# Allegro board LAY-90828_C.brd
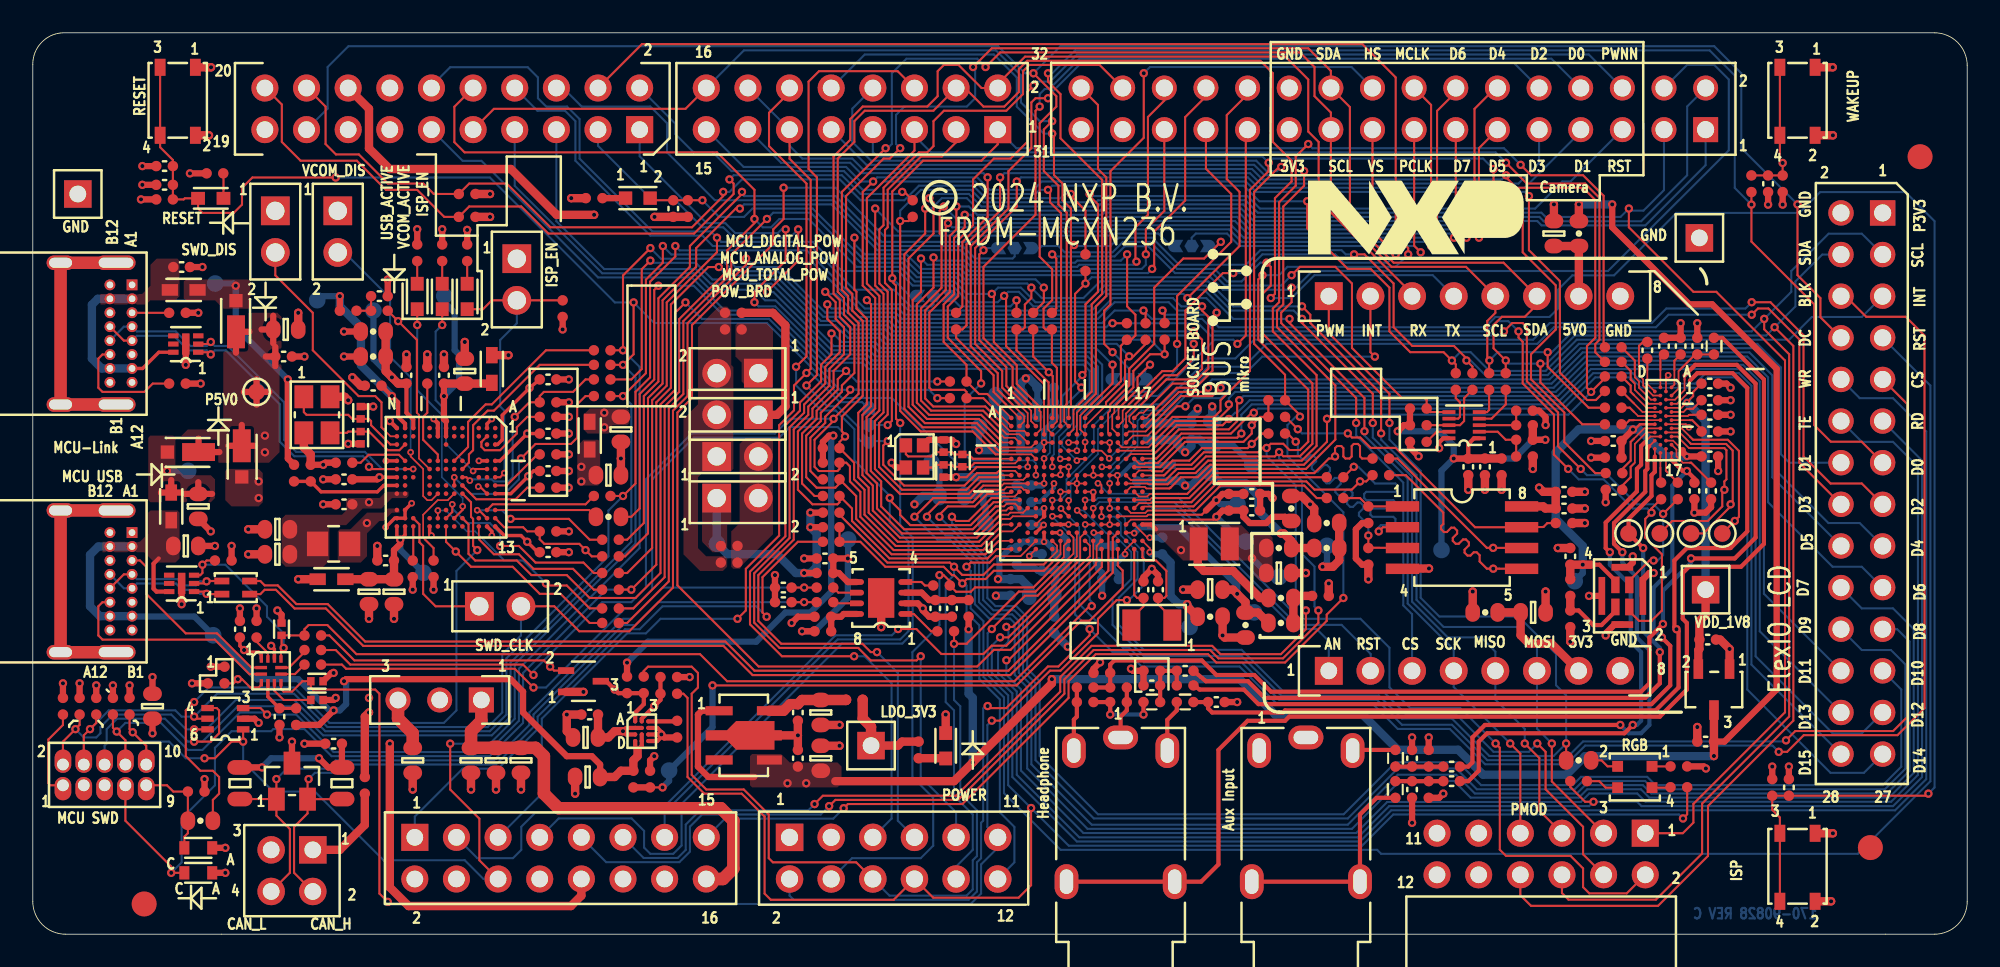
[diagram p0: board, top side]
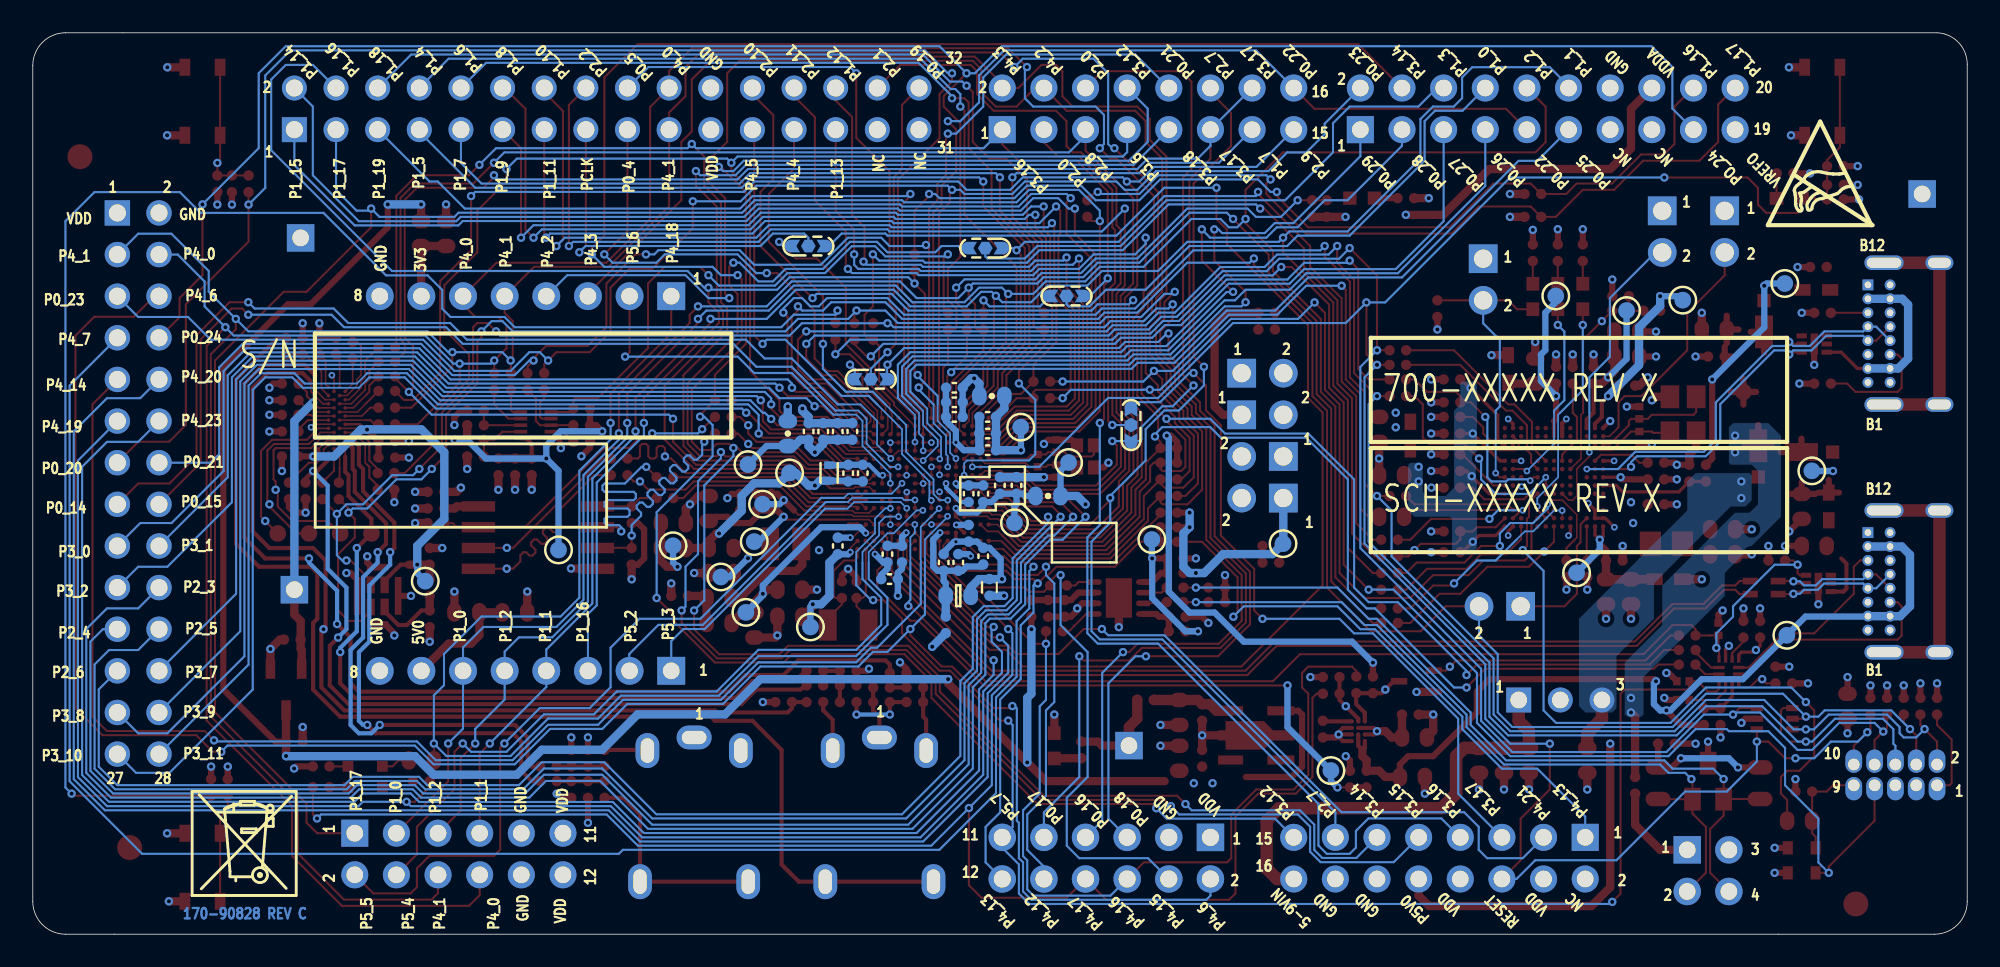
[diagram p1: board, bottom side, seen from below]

Outline 118 x 55 mm; copper layers: TOP, GND, POWER, BOTTOM. Coordinates in mm from the lower left corner of the outline.
Outline path: 0,53.08 0,2 arc(0.59,0.59) 2,0 116,0 arc(117.41,0.59) 118,2 118,53 arc(117.41,54.41) 116,55 1.84,55 arc(0.53,54.41) 0,53.08

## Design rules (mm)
constraint set DEFAULT: min track width 0.127
net group DIFFPAIR6: nets MCU_HS_USB1_DM MCU_HS_USB1_DP
net group DIFFPAIR7: nets MCU_USB1_DM MCU_USB1_DP
net group DIFFPAIR8: nets HS_USB1_DM HS_USB1_DP

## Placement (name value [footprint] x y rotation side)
BH1  125  [MH125-160]  3 3 0 top
BH2  125  [MH125-160]  115 52 0 top
BH3  125  [MH125-160]  115 3 0 top
BH4  125  [MH125-160]  3 52 0 top
C1  4.7uF  [CC0603_OV]  48.07 10.74 90 top
C2  0.1UF  [CC0402_25]  46.67 10.74 90 top
C3  0.1UF  [CC0402_25]  46.67 13.53 270 top
C4  10uF  [CC0603_OV]  48.07 13.53 270 top
C5  4.7uF  [CC0603_OV]  15.43 36.9 0 top
C6  0.1UF  [CC0402_25]  15.3 35.25 0 top
C7  1uF  [CC0402_25]  102.04 11.75 180 top
C8  1uF  [CC0402_25]  102.17 17.97 0 top
C9  0.1UF  [CC0402_25]  60.02 23.07 270 bottom
C10  1uF  [CC0402_25]  59.01 27.38 90 bottom
C11  0.1UF  [CC0402_25]  60.02 26.88 90 bottom
C12  0.1UF  [CC0402_25]  57.99 27.38 90 bottom
C13  1uF  [CC0402_25]  70.67 30.67 90 bottom
C14  0.1UF  [CC0402_25]  68.9 30.67 90 bottom
C15  0.1UF  [CC0402_25]  68.26 28.13 90 bottom
C16  0.1UF  [CC0402_25]  68.01 30.67 90 bottom
C17  0.1UF  [CC0402_25]  69.79 30.67 90 bottom
C18  4.7 uF  [CC0402_TOL0P15]  69.42 28.15 90 bottom
C19  0.1UF  [CC0402_25]  67.37 28.13 90 bottom
C20  0.1UF  [CC0402_25]  68.9 23.69 90 bottom
C21  1uF  [CC0402_25]  59.75 29.53 0 bottom
C22  0.1UF  [CC0402_25]  59.75 31.56 0 bottom
C23  0.1UF  [CC0402_25]  59.75 30.55 0 bottom
C24  1uF  [CC0402_25]  65.74 21.67 0 bottom
C25  0.1UF  [CC0402_25]  61.78 32.45 0 bottom
C26  0.1UF  [CC0402_25]  61.78 33.34 0 bottom
C27  0.1UF  [CC0402_25]  61.78 31.56 0 bottom
C28  2.2UF  [CC0402_25]  74.36 26.86 0 top
C29  0.22uF  [CC0402_25]  61.55 22.68 270 bottom
C30  1uF  [CC0402_25]  74.36 25.85 0 top
C31  1uF  [CC0402_25]  62.44 22.68 270 bottom
C32  4.7uF  [CC0603_OV]  71.82 21.02 180 top
C33  0.1UF  [CC0402_25]  65.86 23.19 270 bottom
C34  6.8uF  [CC0603_OV]  76.01 22.04 0 top
C35  0.1UF  [CC0402_25]  60.91 26.88 90 bottom
C36  4.7uF  [CC0603_OV]  9.33 23.69 0 top
C38  10uF  [CC0603_OV]  33.72 12.01 180 top
C39  0.1UF  [CC0402_25]  33.97 13.4 180 top
C40  4.7uF  [CC0603_OV]  10.1 26.1 270 top
C41  4.7uF  [CC0603_OV]  33.84 9.59 180 top
C42  1uF  [CC0402_25]  102.3 33.6 0 top
C43  1uF  [CC0402_25]  102.3 30.67 0 top
C44  1uF  [CC0402_25]  102.3 29.15 0 top
C45  1uF  [CC0402_25]  96.41 30.09 180 top
C46  100PF  [CC0402_25]  72.2 14.16 0 top
C47  0.1UF  [CC0402_25]  96.46 27.12 180 top
C48  1uF  [CC0402_25]  102.3 31.69 0 top
C49  100PF  [CC0402_25]  101.54 35.88 90 top
C50  1uF  [CC0402_25]  102.37 27.05 270 top
C51  1uF  [CC0402_25]  100.52 35.88 90 top
C52  1uF  [CC0402_25]  98.49 35.63 90 top
C53  1uF  [CC0402_25]  101.36 27.05 270 top
C54  100PF  [CC0402_25]  68.26 15.18 180 top
C55  1uF  [CC0402_25]  99.5 35.88 90 top
C56  1uF  [CC0402_25]  86.55 10.23 0 top
C57  1uF  [CC0402_25]  86.55 9.34 0 top
C58  1uF  [CC0402_25]  102.3 32.58 180 top
C59  100PF  [CC0402_25]  84.14 10.74 90 top
C60  100PF  [CC0402_25]  84.14 8.83 270 top
C61  1uF  [CC0402_25]  70.29 16.07 0 top
C62  0.1UF  [CC0402_25]  93.79 23.05 90 top
C63  10uF  [CC0603_OV]  35.88 30.8 270 top
C64  10uF  [CC0603_OV]  35.11 28.01 0 top
C65  0.1UF  [CC0402_25]  31.43 23.31 0 top
C66  0.1UF  [CC0402_25]  20.76 33.47 180 top
C67  0.1UF  [CC0402_25]  31.43 28.26 0 top
C68  0.1UF  [CC0402_25]  31.43 30.55 0 top
C69  0.1UF  [CC0402_25]  21.14 38.93 0 top
C70  0.1UF  [CC0402_25]  25.08 34.1 90 top
C71  47pF  [CC0603_OV]  26.35 34.36 90 top
C72  47pF  [CC0603_OV]  14.92 24.71 180 top
C73  0.1UF  [CC0402_25]  18.99 26.23 180 top
C74  22uF  [CC0603_OV]  14.92 23.18 180 top
C75  22uF  [CC0603_OV]  20.51 20.9 270 top
C76  0.1UF  [CC0402_25]  21.53 22.8 180 top
C77  47pF  [CC0603_OV]  22.03 20.9 270 top
C78  12PF  [0402_CC]  20 30.29 270 top
C79  12PF  [0402_CC]  20 31.82 90 top
C80  0.1UF  [CC0402_25]  18.99 27.75 180 top
C81  0.1UF  [CC0402_25]  31.43 33.85 0 top
C82  2.2UF  [CC0402_25]  9.08 40.71 0 top
C83  0.1UF  [CC0402_25]  22.8 34.1 90 top
C85  10uF  [CC0603_OV]  7.3 13.91 270 top
C86  1000pF  [CC0402_25]  8.04 46.87 180 top
C87  0.1UF  [CC0402_25]  8.04 45.72 180 top
C88  1000pF  [CC0402_25]  107.12 8.96 90 top
C90  1000pF  [CC0402_25]  105.85 45.79 270 top
C94  12PF  [CC0402_25]  68.64 21.02 90 top
C95  12PF  [CC0402_25]  67.75 21.02 90 top
C96  4.7PF  [0402_CC]  55.56 29.79 90 top
C97  4.7PF  [0402_CC]  55.56 28.26 270 top
C98  0.1UF  [CC0402_25]  87.57 28.52 270 top
C99  1uF  [CC0402_25]  88.58 28.52 270 top
C100  0.1UF  [CC0402_25]  39.07 44.27 270 top
C101  1uF  [CC0402_25]  48.32 22.93 180 top
C102  0.1UF  [CC0402_25]  55.05 19.88 270 top
C103  1uF  [CC0402_25]  56.07 19.88 270 top
C104  56PF  [CC0402_25]  45.78 20.26 0 top
C105  0.01UF  [CC0402_25]  18.35 11.62 180 top
C106  1uF  [CC0402_25]  93.41 25.98 0 top
C107  0.1UF  [CC0402_25]  93.41 26.99 0 top
C108  56PF  [CC0402_25]  45.78 21.15 180 top
C109  10uF  [CC0603_OV]  61.55 20.65 0 bottom
C110  10uF  [CC0603_OV]  28.26 10.61 270 top
C111  10uF  [CC0603_OV]  29.78 10.61 270 top
C112  10uF  [CC0603_OV]  26.73 10.61 270 top
C113  10uF  [CC0603_OV]  23.18 10.61 270 top
C114  10uF  [CC0603_OV]  91.52 19.64 0 top
C115  10uF  [CC0603_OV]  92.79 42.75 90 top
C150  0.1UF  [CC0402_25]  15.05 13.28 270 top
C154  0.1UF  [CC0402_25]  12.64 18.61 90 top
D1  MSS1P3L  [SMB_2P7X1P4]  9.46 29.42 180 top
D2  MSS1P3L  [SMB_2P7X1P4]  12.39 37.4 90 top
D3  GREEN  [LED_0603]  55.69 11.5 90 top
D4  MSS1P3L  [SMB_2P7X1P4]  12.75 29.15 270 top
D6  GREEN  [LED_0603]  23.45 38.91 270 top
D7  RED  [LED_0603]  26.5 38.91 270 top
D8  GREEN  [LED_0603]  24.97 38.91 270 top
D9  PESD3V3S1UB  [SOD523]  10.1 3.75 0 top
D10  PESD3V3S1UB  [SOD523]  10.1 5.27 0 top
D11  PESD3V3L5UY  [SOT-363_0P65_SMT]  11.75 13.15 180 top
D12  RED  [LED_0603]  10.86 44.9 180 top
D13  RGB  [LED4_2P7X2P6_SM]  97.73 9.59 180 top
D14  NUP2105L  [SOT-23]  15.81 9.34 0 top
J1  CON 2x8  [CON_2X8_SKT_100_TH]  58.86 49.09 180 top
J2  CON 2x10  [CON_SKT2X10_TH]  37.02 49.09 270 top
J3  CON 2x8  [CON_2X8_SKT_100_TH]  23.3 5.91 0 top
J4  CON 2x6  [CON_SKT2X6_TH_126L]  46.16 5.91 180 top
J5  SKT_1X8  [CON_1X8_SKT_2P54_TH_126L]  79.06 38.93 90 top
J6  SKT_1X8  [CON_1X8_SKT_2P54_TH_126L]  79.06 16.07 90 top
J7  PPPC062LJBN-RC  [SKT2X6_100_TH_RA]  98.36 6.16 270 top
J8  CON 2x14  [CON_SKT2X14_TH_126L]  112.84 44.01 0 top
J9  CON 2x16  [CON_SKT_32F_100_TH]  102.04 49.09 270 top
J10  USB_TYPE_C  [CON16_USB_TYPE-C_RA_TH]  6.05 39.62 270 top
J11  USB_TYPE_C  [CON16_USB_TYPE-C_RA_TH]  6.05 24.51 270 top
J12  HDR 2X5  [HDR_5X2_FTSH_TH]  1.84 9.08 90 top
J13  HDR 2X2  [HDR202_100_TH]  17.08 5.15 270 top
J14  3.5mm JACK  [CON5_JACK_RA_TH]  66.36 12.01 90 top
J15  HDR 1X1  [HDR101]  51.13 11.51 90 top
J16  HDR 1X1  [HDR101]  101.66 42.49 0 top
J17  HDR 1X1  [HDR101]  2.75 45.16 0 top
J19  HDR_1X3  [HDR103]  27.36 14.29 270 top
J20  HDR 1X1  [HDR101]  102.04 21.02 0 top
J21  3.5mm JACK  [CON5_JACK_RA_TH]  77.66 12.01 90 top
JP1  HDR1X2  [HDR1X2_5P48X2P69]  41.72 26.61 0 top
JP2  HDR1X2  [HDR1X2_5P48X2P69]  41.72 29.15 0 top
JP3  HDR1X2  [HDR1X2_5P48X2P69]  44.26 34.23 180 top
JP4  HDR1X2  [HDR1X2_5P48X2P69]  44.26 31.69 180 top
JP5  HDR1X2  [HDR1X2_5P48X2P69]  29.53 41.22 270 top
JP6  HDR1X2  [HDR1X2_5P48X2P69]  18.6 44.14 270 top
JP7  HDR1X2  [HDR1X2_5P48X2P69]  14.79 44.14 270 top
JP8  HDR1X2  [HDR1X2_5P48X2P69]  27.24 20.01 0 top
L1  120 Ohm  [IND_0402]  59.64 21.16 90 bottom
L2  1.5uH  [IND2_2P7X2P2_1P2_SM]  72.07 23.82 180 top
L3  300Ohms@100MHz  [IND_1P8X1MM_SM]  8.44 26.1 90 top
L4  90OHM  [IND4_CHOKE_0805]  12.38 21.15 0 top
L6  220 OHM  [IND_0402]  70.29 14.16 0 top
L7  220 OHM  [IND_0402]  102.55 35.88 270 top
L8  220 OHM  [IND_0402]  68.26 14.16 0 top
L9  220 OHM  [IND_0402]  83.12 10.74 270 top
L10  220 OHM  [IND_0402]  83.12 8.83 90 top
L11  600OHM  [IND_1P8X1MM_SM]  33.97 30.42 270 top
L12  600OHM  [IND_1P8X1MM_SM]  28 34.48 270 top
L13  600OHM  [IND_1P8X1MM_SM]  18.22 21.66 0 top
L14  4.7uH  [IND_0805]  18.35 23.82 180 top
L15  300Ohms@100MHz  [IND_1P8X1MM_SM]  9.2 39.31 0 top
NOREF  -  []  2.02 1.36 0 top
NOREF#2  -  []  77.16 -0.29 90 top
NOREF#3  -  []  -262.98 261.03 0 top
NOREF#4  -  []  69.71 41.99 0 top
NOREF#5  -  []  67.69 23.5 90 top
NOREF#6  -  []  96.54 19.97 90 top
NOREF#7  -  []  16.43 -13.82 0 top
NOREF#8  -  []  1.69 17.21 0 top
NOREF#9  -  []  65.9 33.86 0 top
NOREF#10  -  []  50.19 32 0 top
NOREF#11  -  []  85.66 3.62 90 top
NOREF#12  -  []  62.3 6.35 0 top
NOREF#13  -  []  36.46 11.55 90 top
NOREF#14  -  []  14.74 15.35 0 top
NOREF#15  -  []  59.19 23 90 top
NOREF#16  -  []  41.72 26.61 0 top
NOREF#17  -  []  112.84 10.99 90 top
NOREF#18  -  []  3.04 49.78 90 top
NOREF#19  -  []  73.91 -0.29 0 top
NOREF#20  -  []  29.53 38.68 90 top
NOREF#21  -  []  66.36 1.71 0 top
NOREF#22  -  []  11.7 15.31 90 top
NOREF#23  -  []  53.97 38.94 0 top
NOREF#24  -  []  62.61 -0.29 0 top
NOREF#25  -  []  13.45 40.13 90 top
NOREF#26  -  []  18.6 41.6 90 top
NOREF#27  -  []  8.36 39.31 0 top
NOREF#28  -  []  27.5 35.38 0 top
NOREF#29  -  []  7.94 25.2 0 top
NOREF#30  -  []  53.78 51.63 0 top
NOREF#31  -  []  -2.71 41.22 0 top
NOREF#32  -  []  28.18 37.21 90 top
NOREF#33  -  []  15.14 15.35 90 top
NOREF#34  -  []  25.84 3.37 0 top
NOREF#35  -  []  106.57 48.74 0 top
NOREF#36  -  []  4.7 18.56 0 top
NOREF#37  -  []  69.36 -2.79 90 top
NOREF#38  -  []  74.66 5.71 0 top
NOREF#39  -  []  83.97 2.12 0 top
NOREF#40  -  []  7.77 48.74 90 top
NOREF#41  -  []  90.82 22.29 90 top
NOREF#42  -  []  72.64 40.4 0 top
NOREF#43  -  []  60.69 24 0 top
NOREF#44  -  []  41.08 49.09 90 top
NOREF#45  -  []  96.68 8.94 90 top
NOREF#46  -  []  45.73 27.56 90 top
NOREF#47  -  []  59.69 23.5 0 top
NOREF#48  -  []  97.19 -36.41 0 top
NOREF#49  -  []  23.3 3.37 0 top
NOREF#50  -  []  33.47 31.32 0 top
NOREF#51  -  []  89.91 21.45 90 top
NOREF#52  -  []  69.71 41.99 0 top
NOREF#53  -  []  6.05 23.66 90 top
NOREF#54  -  []  73.91 -0.29 0 top
NOREF#55  -  []  41.72 31.69 0 top
NOREF#56  -  []  69.42 27.67 90 top
NOREF#57  -  []  45.73 30.1 90 top
NOREF#58  -  []  13.71 15.25 0 top
NOREF#59  -  []  89.91 21.45 90 top
NOREF#60  -  []  1.69 32.32 0 top
NOREF#61  -  []  100.77 24.83 0 top
NOREF#62  -  []  36.75 11.79 0 top
NOREF#63  -  []  6.44 41.22 90 top
NOREF#64  -  []  62.61 -0.29 0 top
NOREF#65  -  []  -2.71 16.96 0 top
NOREF#66  -  []  65.9 33.86 0 top
NOREF#67  -  []  7.94 24.2 90 top
NOREF#68  -  []  55.28 26.67 90 top
NOREF#69  -  []  41.87 13.63 0 top
NOREF#70  -  [unnamed#2]  112.09 5.29 0 top
NOREF#71  -  []  69.1 27.57 0 top
NOREF#72  -  []  96.37 10.84 0 top
NOREF#73  -  []  53.97 38.94 0 top
NOREF#74  -  []  63.36 -2.79 0 top
NOREF#75  -  []  8.44 25.26 90 top
NOREF#76  -  []  63.51 11.21 0 top
NOREF#77  -  []  -287.62 -260.56 0 top
NOREF#78  -  []  42.07 9.83 90 top
NOREF#79  -  []  17.32 21.16 90 top
NOREF#80  -  []  10.68 15.05 0 top
NOREF#81  -  []  67.55 6.35 90 top
NOREF#82  -  []  41.08 3.37 90 top
NOREF#83  -  []  17.38 21.66 0 top
NOREF#84  -  []  106.57 48.74 90 top
NOREF#85  -  []  16.43 -13.82 90 top
NOREF#86  -  []  1.69 32.32 90 top
NOREF#87  -  []  40.25 19.79 0 top
NOREF#88  -  []  17.26 40.13 0 top
NOREF#89  -  []  62.61 -0.29 0 top
NOREF#90  -  []  84.47 21.44 0 top
NOREF#91  -  []  45.73 27.56 0 top
NOREF#92  -  []  4.7 33.67 0 top
NOREF#93  -  []  42.07 9.83 0 top
NOREF#94  -  []  90.82 22.29 90 top
NOREF#95  -  []  66.36 8.71 0 top
NOREF#96  -  []  117.66 54.12 0 top
NOREF#97  -  []  112.84 41.47 90 top
NOREF#98  -  []  37.55 11.79 90 top
NOREF#99  -  []  102.55 13.68 90 top
NOREF#100  -  []  41.72 34.23 0 top
NOREF#101  -  []  17.26 40.13 90 top
NOREF#102  -  []  90.82 22.29 90 top
NOREF#103  -  []  36.75 11.79 0 top
NOREF#104  -  []  101.85 3.04 90 top
NOREF#105  -  []  90.82 22.29 90 top
NOREF#106  -  []  83.55 22.29 0 top
NOREF#107  -  []  28.5 33.58 90 top
NOREF#108  -  []  3 3 0 top
NOREF#109  -  []  41.08 51.63 0 top
NOREF#110  -  []  101.85 49.78 90 top
NOREF#111  -  []  74.81 11.21 0 top
NOREF#112  -  []  7.77 48.74 0 top
NOREF#113  -  []  95.71 20.64 0 top
NOREF#114  -  []  1.69 17.21 90 top
NOREF#115  -  []  101.6 16.18 0 top
NOREF#116  -  []  28 33.64 90 top
NOREF#117  -  []  73.91 -0.29 0 top
NOREF#118  -  []  58.92 41.86 0 top
NOREF#119  -  []  67.19 26 90 top
NOREF#120  -  []  95.82 6.16 0 top
NOREF#121  -  []  40.25 22.33 0 top
NOREF#122  -  []  37.55 11.79 90 top
NOREF#123  -  []  55.32 44.91 0 top
NOREF#124  -  []  25.77 13.18 0 top
NOREF#125  -  []  13.45 40.13 0 top
NOREF#126  -  []  70.72 24.92 0 top
NOREF#127  -  []  51.01 30.09 90 top
NOREF#128  -  []  15.15 15.87 90 top
NOREF#129  -  []  40.25 22.33 90 top
NOREF#130  -  []  34.78 12.93 0 top
NOREF#131  -  []  63.06 3.21 0 top
NOREF#132  -  []  6.05 38.77 90 top
NOREF#133  -  []  25.77 13.18 90 top
NOREF#134  -  []  59.9 41.86 0 top
NOREF#135  -  []  70.72 22.72 90 top
NOREF#136  -  []  101.85 52.98 0 top
NOREF#137  -  []  94.91 18.59 90 top
NOREF#138  -  []  13.93 15.87 0 top
NOREF#139  -  []  73.91 7.21 0 top
NOREF#140  -  []  73.91 7.21 0 top
NOREF#141  -  []  -2.71 16.96 90 top
NOREF#142  -  []  3.04 52.98 0 top
NOREF#143  -  []  101.85 6.24 0 top
NOREF#144  -  []  104.1 12.73 90 top
NOREF#145  -  []  11.95 15.05 90 top
NOREF#146  -  []  96.96 18.89 90 top
NOREF#147  -  []  -2.5 -180.55 0 top
NOREF#148  -  []  40.25 19.79 90 top
NOREF#149  -  []  3 3 0 top
NOREF#150  -  []  27.24 20.01 0 top
NOREF#151  -  []  74.36 3.21 0 top
NOREF#152  -  []  96.54 21.32 0 top
NOREF#153  -  []  83.97 3.67 0 top
NOREF#154  -  []  70.25 27.57 90 top
NOREF#155  -  []  84.47 21.44 0 top
NOREF#156  -  []  55.28 26.67 0 top
NOREF#157  -  []  41.72 29.15 0 top
NOREF#158  -  []  34.47 29.52 90 top
NOREF#159  -  []  104.1 12.73 0 top
NOREF#160  -  []  0 49.58 0 top
NOREF#161  -  []  51.01 31.07 90 top
NOREF#162  -  []  92.67 2.12 90 top
NOREF#163  -  []  8.3 38.81 90 top
NOREF#164  -  [unnamed#2]  6.79 1.85 0 top
NOREF#165  -  []  14.79 41.6 90 top
NOREF#166  -  []  106.57 2.01 0 top
NOREF#167  -  []  83.55 22.29 0 top
NOREF#168  -  []  63.94 51.63 0 top
NOREF#169  -  []  10.68 15.31 0 top
NOREF#170  -  []  8.3 39.81 0 top
NOREF#171  -  []  15.36 15.25 90 top
NOREF#172  -  [unnamed#2]  115.12 47.44 0 top
NOREF#173  -  []  77.8 41.48 0 top
NOREF#174  -  []  106.57 2.01 90 top
NOREF#175  -  []  33.97 29.58 90 top
NOREF#176  -  []  96.37 8.34 90 top
NOREF#177  -  []  71.12 23.82 0 top
NOREF#178  -  []  96.68 8.94 0 top
NOREF#179  -  []  41.87 10.63 0 top
NOREF#180  -  []  45.73 30.1 0 top
NOREF#181  -  []  72.64 40.4 90 top
NOREF#182  -  []  108.31 0 90 top
NOREF#183  -  []  28.18 37.21 0 top
NOREF#184  -  []  17.32 22.16 0 top
NOREF#185  -  []  36.38 30.04 180 bottom
NOREF#186  -  []  100.77 24.83 180 bottom
NOREF#187  -  []  100.79 30.3 180 bottom
NOREF#188  -  []  108.28 2.36 180 bottom
NOREF#189  -  []  12.14 43.26 180 bottom
NOREF#190  -  []  36.38 23.31 180 bottom
Q1  2SK3018  [SOT323_3]  33.59 15.43 270 top
Q2  ALS-PT19-315C/L177/TR8  [PHTRANS_1P9X1]  36.91 44.91 0 top
R2  0  [RC0402_25]  69.04 36.78 90 top
R4  0  [RC0402_25]  66.74 36.77 90 top
R5  0  [RC0402_25]  67.88 36.77 90 top
R6  4.7K  [RC0402_25]  26.49 45.16 180 top
R7  4.7K  [RC0402_25]  26.49 43.77 180 top
R8  0  [RC0402_25]  50.12 14.3 0 top
R12  0  [RC0402_25]  104.84 45.79 90 top
R13  0  [RC0402_25]  87.82 33.72 270 top
R14  0  [RC0402_25]  62.17 37.41 90 top
R15  0  [RC0402_25]  60.01 37.41 90 top
R18  0  [RC0402_25]  86.8 33.72 270 top
R22  0  [RC0402_25]  56.32 37.41 90 top
R23  0  [RC0402_25]  60.91 24.46 90 bottom
R24  0  [RC0402_25]  64.98 23.19 90 bottom
R25  0  [RC0402_25]  55.43 21.28 180 top
R31  0  [RC0402_25]  79.44 26.61 0 top
R32  0  [RC0402_25]  82.23 28.01 0 top
R33  0  [RC0402_25]  82.23 29.02 0 top
R34  0  [RC0402_25]  79.44 27.88 0 top
R35  0  [RC0402_25]  75.88 31.56 0 top
R36  0  [RC0402_25]  75.88 30.55 0 top
R37  0  [RC0402_25]  75.88 32.58 0 top
R38  0  [RC0402_25]  61.02 37.41 270 top
R39  0  [RC0402_25]  64.21 40.97 90 top
R40  0  [RC0402_25]  53.67 44.27 90 top
R43  4.7K  [RC0402_25]  48.7 28.77 0 top
R44  4.7K  [RC0402_25]  48.7 29.66 0 top
R49  0  [RC0402_25]  89.85 33.72 270 top
R50  0  [RC0402_25]  88.84 33.72 270 top
R53  0  [RC0402_25]  56.45 32.71 0 top
R54  0  [RC0402_25]  56.45 33.72 0 top
R55  0  [RC0402_25]  48.7 27.75 0 top
R56  0  [RC0402_25]  48.7 26.74 0 top
R57  0  [RC0402_25]  48.7 23.94 180 top
R64  0  [RC0402_25]  62.31 18.87 90 bottom
R67  0  [RC0402_25]  55.69 18.48 180 top
R69  0  [RC0402_25]  42.48 23.69 180 top
R70  470  [RC0402_25]  54.04 11.24 270 top
R71  0  [RC0402_25]  42.48 22.67 180 top
R72  0  [RC0402_25]  42.73 36.9 0 top
R73  0  [RC0402_25]  42.73 37.91 0 top
R74  0  [RC0603_OV]  56.07 26.74 0 bottom
R75  0  [RC0603_OV]  71.94 30.55 270 bottom
R76  0  [RC0603_OV]  71.82 19.37 180 top
R77  0  [RC0603_OV]  59.5 32.83 180 bottom
R78  0  [RC0603_OV]  76.77 25.98 270 top
R79  0  [RC0603_OV]  73.98 18.86 90 top
R80  0  [RC0603_OV]  76.14 18.99 0 top
R81  0  [RC0603_OV]  76.14 20.51 180 top
R82  0  [RC0402_25]  72.96 26.36 90 top
R83  0  [RC0603_OV]  76.01 23.56 180 top
R84  0  [RC0603_OV]  78.93 23.56 180 top
R85  0  [RC0603_OV]  78.93 25.09 0 top
R86  10K  [RC0402_25]  78.55 20.64 0 top
R87  47K  [RC0402_25]  38.8 15.69 180 top
R88  0  [RC0402_25]  38.8 14.67 180 top
R89  0  [RC0402_25]  36.64 9.47 270 top
R90  4.7K  [RC0402_25]  36.25 15.22 270 top
R91  20K  [RC0402_25]  37.65 9.47 90 top
R92  0  [RC0402_25]  37.27 15.22 270 top
R93  10K  [RC0402_25]  11.62 22.8 0 top
R94  100K  [RC0402_25]  39.31 12.51 270 top
R95  0  [RC0402_25]  96.41 29.08 0 top
R96  0  [RC0402_25]  99.33 27.05 90 top
R97  0  [RC0402_25]  64.2 15.05 0 top
R98  0  [RC0402_25]  66.23 15.05 0 top
R99  0  [RC0402_25]  100.34 27.05 90 top
R100  0  [RC0402_25]  65.21 15.94 0 top
R101  0  [RC0402_25]  64.2 14.16 0 top
R102  0  [RC0402_25]  66.23 14.16 0 top
R103  33  [RC0402_25]  96.46 28.13 180 top
R104  0  [RC0402_25]  96.41 32.13 0 top
R105  0  [RC0402_25]  96.41 31.11 0 top
R106  0  [RC0402_25]  96.41 35.81 0 top
R107  0  [RC0402_25]  96.41 33.14 0 top
R108  0  [RC0402_25]  96.41 34.03 0 top
R109  0  [RC0402_25]  96.41 34.92 0 top
R110  2.2K  [RC0402_25]  70.29 15.18 180 top
R111  47K  [RC0402_25]  85.15 10.74 270 top
R112  47K  [RC0402_25]  85.15 8.83 90 top
R113  47K  [RC0402_25]  68.26 16.07 180 top
R116  10K  [RC0402_25]  19.24 38.04 0 top
R117  100  [RC0402_25]  21.14 38.04 0 top
R118  510  [RC0402_25]  23.45 41.58 270 top
R119  510  [RC0402_25]  26.5 41.58 270 top
R120  510  [RC0402_25]  24.97 41.58 270 top
R121  0  [RC0402_25]  15.94 28.13 270 top
R122  20K  [RC0402_25]  16.95 28.13 90 top
R125  2.0K  [RC0603_OV]  20.76 36.77 0 top
R126  2.0K  [RC0603_OV]  20.76 35.25 180 top
R127  100K  [RC0402_25]  32.32 38.17 90 top
R130  1K  [RC0402_25]  31.43 27.25 0 top
R132  1K  [RC0402_25]  23.18 22.29 270 top
R133  1K  [RC0402_25]  31.43 29.28 0 top
R134  1K  [RC0402_25]  24.45 22.29 270 top
R135  1K  [RC0402_25]  31.43 31.56 0 top
R136  1K  [RC0402_25]  18.99 28.77 180 top
R137  1K  [RC0402_25]  24.07 34.1 90 top
R139  0  [RC0402_25]  34.73 26.74 0 top
R140  0  [RC0402_25]  34.73 34.74 0 top
R141  0  [RC0402_25]  35.24 21.02 0 top
R142  0  [RC0402_25]  34.73 32.83 0 top
R143  0  [RC0402_25]  34.73 35.63 0 top
R144  100  [RC0402_25]  1.84 13.91 270 top
R145  100K  [RC0402_25]  2.86 13.91 270 top
R146  100K  [RC0402_25]  4.89 13.91 270 top
R147  100K  [RC0402_25]  5.9 13.91 270 top
R148  2.0K  [RC0603_OV]  10.22 6.93 180 top
R149  100K  [RC0402_25]  3.87 13.91 90 top
R150  2.2K  [RC0402_25]  9.97 8.7 0 top
R153  0  [RC0402_25]  35.24 22.04 180 top
R154  0  [RC0402_25]  35.24 19.88 180 top
R155  0  [RC0402_25]  35.24 24.07 180 top
R156  0  [RC0402_25]  35.24 18.99 180 top
R157  2.2K  [RC0402_25]  31.43 24.58 180 top
R158  2.2K  [RC0402_25]  31.43 32.45 180 top
R159  0  [RC0402_25]  35.24 23.05 180 top
R160  0  [RC0402_25]  34.73 33.85 180 top
R161  10K  [RC0402_25]  8.04 44.83 0 top
R162  10K  [RC0402_25]  106.11 8.96 270 top
R163  470  [RC0402_25]  11.11 46.42 0 top
R164  10K  [RC0402_25]  106.74 45.79 90 top
R166  0  [RC0402_25]  100.41 10.24 180 top
R167  680  [RC0603_OV]  94.3 10.61 180 top
R168  470  [RC0402_25]  94.3 9.34 180 top
R169  470  [RC0402_25]  100.41 8.97 0 top
R170  1M  [0402_CC]  56.7 28.9 270 top
R171  0  [RC0402_25]  89.6 28.52 90 top
R172  0  [RC0402_25]  34.24 44.91 180 top
R173  4.7K  [RC0402_25]  84.52 31.06 0 top
R174  4.7K  [RC0402_25]  84.52 32.07 0 top
R175  10K  [RC0402_25]  90.99 30.17 0 top
R176  10K  [RC0402_25]  90.99 29.15 180 top
R178  15K  [RC0402_25]  39.96 44.27 270 top
R179  0  [RC0402_25]  57.09 19.88 90 top
R180  0  [RC0402_25]  48.32 22.04 180 top
R181  10K  [RC0402_25]  48.2 18.48 0 top
R182  0  [RC0402_25]  20.26 9.08 90 top
R183  0  [RC0402_25]  48.32 20.26 0 top
R184  62  [RC0805_OV]  18.86 9.21 90 top
R185  100K  [RC0402_25]  48.2 19.37 180 top
R186  10K  [RC0402_25]  93.41 25.09 180 top
R187  10K  [RC0402_25]  81.47 25.59 90 top
R188  10K  [RC0402_25]  81.47 23.05 90 top
R189  62  [RC0805_OV]  12.64 9.21 270 top
R190  0  [RC0402_25]  48.32 21.15 0 top
R191  10K  [RC0402_25]  90.99 31.94 0 top
R197  10K  [RC0402_25]  84.52 30.04 0 top
R202  100K  [RC0402_25]  90.99 31.06 180 top
R203  0  [RC0402_25]  93.79 21.15 270 top
R204  0  [RC0402_25]  93.79 19.24 90 top
R206  0  [RC0603_OV]  88.6 19.64 0 top
R207  0  [RC0603_OV]  94.31 42.75 270 top
R210  0  [RC0402_25]  17.08 16.45 0 top
R211  0  [RC0402_25]  17.08 17.34 0 top
R213  5.1K  [RC0402_25]  8.83 33.6 0 top
R214  5.1K  [RC0402_25]  8.83 37.91 0 top
R216  220  [RC0603_OV]  35.11 25.47 180 top
R257  10K  [0402_CC]  17.33 15.43 180 top
R265  10K  [0402_CC]  15.18 18.61 270 top
R276  0  [RC0402_25]  16.06 13.28 270 top
R278  4.7K  [RC0402_25]  13.65 18.61 270 top
R294  10K  [0402_CC]  17.33 14.29 180 top
R295  0  [RC0402_25]  17.08 18.23 0 top
R297  0  [RC0402_X3]  11.7 15.81 270 top
R298  4.7K  [RC0402_25]  48.7 24.83 0 top
R299  4.7K  [RC0402_25]  48.7 25.72 0 top
SJ1  3 PIN 0402 JUMPER  [3PIN_0402X2_A]  59.9 41.86 180 bottom
SJ2  3 PIN 0402 JUMPER  [3PIN_0402X2_A]  54.94 38.94 0 bottom
SJ3  3 PIN 0402 JUMPER  [3PIN_0402X2_A]  51.01 31.07 270 bottom
SJ4  3 PIN 0402 JUMPER  [3PIN_0402X2_A]  70.69 41.99 0 bottom
SJ5  3 PIN 0402 JUMPER  [3PIN_0402X2_A]  66.88 33.86 0 bottom
SW1  SW SPST NO  [SW4_4P15_4P2X3P2_SM]  8.84 50.88 270 top
SW2  SW SPST NO  [SW4_4P15_4P2X3P2_SM]  107.65 50.88 270 top
SW3  SW SPST NO  [SW4_4P15_4P2X3P2_SM]  107.65 4.14 270 top
TP2  -  [TPAD_040]  13.65 33.09 0 top
TP5  -  [TPAD_040]  103.06 24.45 0 top
TP6  -  [TPAD_040]  97.34 24.45 180 top
TP8  -  [TPAD_040]  101.15 24.45 270 top
TP9  -  [TPAD_040]  99.25 24.45 270 top
TP10  -  [TPAD_040]  20.78 38.05 180 bottom
TP11  -  [TPAD_040]  76.02 21.8 180 bottom
TP12  -  [TPAD_040]  17.35 38.69 180 bottom
TP13  -  [TPAD_040]  11.13 39.7 180 bottom
TP14  -  [TPAD_040]  9.48 28.27 180 bottom
TP15  -  [TPAD_040]  38.81 9.98 180 bottom
TP16  -  [TPAD_040]  11 18.24 180 bottom
TP17  -  [TPAD_040]  23.83 22.05 180 bottom
TP18  -  [TPAD_040]  94.06 21.54 180 bottom
TP19  -  [TPAD_040]  71.83 28.15 180 bottom
TP20  -  [TPAD_040]  73.48 26.24 180 bottom
TP21  -  [TPAD_040]  25.1 38.94 180 bottom
TP22  -  [TPAD_040]  49.74 24.08 180 bottom
TP23  -  [TPAD_040]  85.93 23.45 180 bottom
TP24  -  [TPAD_040]  41.73 23.83 180 bottom
TP25  -  [TPAD_040]  74.5 19.64 180 bottom
TP26  -  [TPAD_040]  78.95 23.7 180 bottom
TP27  -  [TPAD_040]  73.99 23.95 180 bottom
TP28  -  [TPAD_040]  54.82 28.78 180 bottom
TP29  -  [TPAD_040]  57.74 30.94 180 bottom
TP30  -  [TPAD_040]  74.37 28.65 180 bottom
TP31  -  [TPAD_040]  58.12 25.1 180 bottom
TP32  -  [TPAD_040]  70.56 18.75 180 bottom
U1  MCXN236VDFT  [BGA184_0P5_9X9_SM]  63.69 27.5 0 top
U2  XC6227C331PR-G  [SOT89-5]  43.37 12.13 270 top
U3  UM1550S-18  [SOT23-3-1P95]  102.55 14.93 180 top
U4  NX5P3090UK  [WLCSP12_0P4_1P38X1P68MM_SMDP]  37.15 12.39 0 top
U5  RClamp0854P.TCT  [SLP1616P6]  9.08 21.4 90 top
U6  DA7212  [CSP34_0P5_4P54X1P66]  99.45 31.36 270 top
U7  SPK0641HT4H-1  [LGA8_3P1X4P1MM_SPK0641]  96.96 20.64 180 top
U8  LPC55S69JEV98  [BGA98_0P5_7X7]  25.21 27.88 270 top
U9  RClamp0854P.TCT  [SLP1616P6]  9.33 36.01 90 top
U10  FXLS8974CFR3  [DFN_10_0P4_2X2]  87.31 31.06 180 top
U11  TJA1057GTK/3Z  [SON8_0P65_3P15X3P15]  51.75 20.51 180 top
U12  W25Q64JVSSIQ  [SO8_W]  87.18 24.2 0 top
U41  PTN5150A  [X2QFN12_0P4_1P6X1P6]  14.54 16.07 0 top
Y1  16MHz  [XTAL4_3P4X2P7_SM]  17.33 31.69 270 top
Y2  32.768KHz  [XTAL2-3P2X1P5-SM]  68.26 18.86 180 top
Y3  24MHz  [XTAL4_2P1X1P7MM_SM]  53.78 29.15 270 top

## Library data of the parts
BH1-BH4 = MOUNT_HOLE
C1-C8 C10 C13 C18 C21 C24 C28-C32 C34 C36 C38-C45 C47 C48 C50-C53 C55-C58 C61-C83 C85-C88 C90 C94-C99 C101-C104 C106 C108-C115 = CAP_NP
C9 C11 C12 C14-C17 C19 C20 C22 C23 C25-C27 C33 C35 C46 C49 C54 C59 C60 C100 C107 C150 C154 = CAP_NP: tolerance: 10%
C105 = CAP_NP: tolerance: 20%
D1 D2 D4 = DIODE_SCHTKY
D3 D6-D8 D12 = LED
D9 D10 = DIODE_TVS
D11 = DIODE_ARRAY_5CH
D13 = LRTBR48G_4P
D14 = DIODE_NUP2105L
J1 J3 = CONN_HDR_8X2
J2 = CONN_HDR_10X2
J4 J7 = CONN_HDR_6X2
J5 J6 = CONN_HDR_8X1
J8 = CONN_HDR_14X2
J9 = CONN_HDR_16X2
J10 J11 = USB16_TYPEC_4SH
J12 = CONN_HDR_5X2
J13 = CONN_HDR_2X2
J14 J21 = 3.5MM_PHONE_JACK
J15-J17 J20 = CONN_HDR_1X1
J19 = CONN_HDR_3X1
JP1-JP8 = CONN_HDR_2X1
L1 L6-L10 = INDUCTOR_FERRITE
L2 = INDUCTOR_B
L3 L11-L15 = INDUCTOR
L4 = DLW43
Q1 = 2SK3018
Q2 = PT12_PHTRANS_2P
R2 R4-R8 R12-R15 R18 R22-R25 R31-R40 R43 R44 R49 R50 R53-R57 R64 R67 R69 R71-R102 R104-R112 R116-R122 R125-R127 R130 R132-R137 R139-R150 R153-R162 R164 R166 R167 R170-R176 R178-R184 R186-R191 R197 R202-R204 R206 R207 R210 R211 R213 R214 R216 R276 R278 R295 R298 R299 = RES
R70 R103 R113 R163 R168 R169 = RES: tolerance: 1%
R185 R257 R265 R294 = RES: tolerance: 5%
R297 = RES_3PIN
SJ1-SJ5 = RES_3PIN_C
SW1-SW3 = SW_PSHBT_SPST_2
TP2 TP5 TP6 TP8-TP32 = TestLoop
U1 = MCXN236VDFT_BGA184_B
U2 = XC6227C_5P
U3 = MCP1700
U4 = NX5P3090UK_WLCSP12
U5 U9 = RCLAMP1654P_NEW
U6 = DA7212_CSP_34P
U7 = SPK0641HT4H_8P
U8 = NIOBE4_MINI_FBGA98
U10 = FXLS8962AF_DFN10
U11 = TJA1051TK_3_HVSON8
U12 = W25Q64JV_SOIC_8P_B
U41 = PTN5150A_X2QFN12
Y1 = XTAL_4P_B
Y2 = CRYSTAL
Y3 = XTAL_4PIN

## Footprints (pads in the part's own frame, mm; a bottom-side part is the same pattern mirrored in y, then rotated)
3PIN_0402X2_A
  custom 0.191x0.191 smd: 1(0.978,0) 2(0,0) 3(-0.978,0)
0402_CC
  rect 0.457x0.508 smd: 1(-0.375,0) 2(0.375,0)
BGA98_0P5_7X7
  round 0.279 smd: A1(-3,3) A2(-2.499,3) A3(-1.999,3) A5(-1.001,3) A6(-0.5,3) A7(0,3) A8(0.5,3) A9(1.001,3) A11(1.999,3) A12(2.499,3) A13(3,3) B1(-3,2.499) B2(-2.499,2.499) B3(-1.999,2.499) B5(-1.001,2.499) B6(-0.5,2.499) B7(0,2.499) B8(0.5,2.499) B9(1.001,2.499) B11(1.999,2.499) B12(2.499,2.499) B13(3,2.499) C1(-3,1.999) C2(-2.499,1.999) C7(0,1.999) C12(2.499,1.999) C13(3,1.999) E1(-3,1.001) E2(-2.499,1.001) E5(-1.001,1.001) E6(-0.5,1.001) E7(0,1.001) E8(0.5,1.001) E9(1.001,1.001) E12(2.499,1.001) E13(3,1.001) F1(-3,0.5) F2(-2.499,0.5) F5(-1.001,0.5) F6(-0.5,0.5) F8(0.5,0.5) F9(1.001,0.5) F12(2.499,0.5) F13(3,0.5) G1(-3,0) G2(-2.499,0) G3(-1.999,0) G5(-1.001,0) G6(-0.5,0) G8(0.5,0) G9(1.001,0) G11(1.999,0) G12(2.499,0) G13(3,0) H1(-3,-0.5) H2(-2.499,-0.5) H5(-1.001,-0.5) H6(-0.5,-0.5) H8(0.5,-0.5) H9(1.001,-0.5) H12(2.499,-0.5) H13(3,-0.5) J1(-3,-1.001) J2(-2.499,-1.001) J5(-1.001,-1.001) J6(-0.5,-1.001) J7(0,-1.001) J8(0.5,-1.001) J9(1.001,-1.001) J12(2.499,-1.001) J13(3,-1.001) L1(-3,-1.999) L2(-2.499,-1.999) L7(0,-1.999) L12(2.499,-1.999) L13(3,-1.999) M1(-3,-2.499) M2(-2.499,-2.499) M3(-1.999,-2.499) M5(-1.001,-2.499) M6(-0.5,-2.499) M7(0,-2.499) M8(0.5,-2.499) M9(1.001,-2.499) M11(1.999,-2.499) M12(2.499,-2.499) M13(3,-2.499) N1(-3,-3) N2(-2.499,-3) N3(-1.999,-3) N5(-1.001,-3) N6(-0.5,-3) N7(0,-3) N8(0.5,-3) N9(1.001,-3) N11(1.999,-3) N12(2.499,-3) N13(3,-3)
BGA184_0P5_9X9_SM
  round 0.279 smd: A1(-4,4) A2(-3.5,4) A4(-2.5,4) A6(-1.5,4) A8(-0.5,4) A10(0.5,4) A12(1.5,4) A14(2.5,4) A16(3.5,4) A17(4,4) B1(-4,3.5) B2(-3.5,3.5) B3(-3,3.5) B4(-2.5,3.5) B6(-1.5,3.5) B7(-1,3.5) B8(-0.5,3.5) B10(0.5,3.5) B11(1,3.5) B12(1.5,3.5) B14(2.5,3.5) B15(3,3.5) B16(3.5,3.5) B17(4,3.5) C3(-3,3) C4(-2.5,3) C5(-2,3) C6(-1.5,3) C8(-0.5,3) C9(0,3) C10(0.5,3) C12(1.5,3) C13(2,3) C14(2.5,3) C15(3,3) D1(-4,2.5) D2(-3.5,2.5) D3(-3,2.5) D4(-2.5,2.5) D6(-1.5,2.5) D7(-1,2.5) D9(0,2.5) D11(1,2.5) D12(1.5,2.5) D14(2.5,2.5) D15(3,2.5) D16(3.5,2.5) D17(4,2.5) E4(-2.5,2) E5(-2,2) E7(-1,2) E8(-0.5,2) E10(0.5,2) E11(1,2) E13(2,2) E14(2.5,2) F1(-4,1.5) F2(-3.5,1.5) F3(-3,1.5) F4(-2.5,1.5) F6(-1.5,1.5) F8(-0.5,1.5) F10(0.5,1.5) F12(1.5,1.5) F14(2.5,1.5) F15(3,1.5) F16(3.5,1.5) F17(4,1.5) G2(-3.5,1) G4(-2.5,1) G5(-2,1) G7(-1,1) G11(1,1) G13(2,1) G14(2.5,1) G16(3.5,1) H1(-4,0.5) H2(-3.5,0.5) H3(-3,0.5) H5(-2,0.5) H6(-1.5,0.5) H8(-0.5,0.5) H9(0,0.5) H10(0.5,0.5) H12(1.5,0.5) H13(2,0.5) H15(3,0.5) H16(3.5,0.5) H17(4,0.5) J3(-3,0) J4(-2.5,0) J8(-0.5,0) J10(0.5,0) J14(2.5,0) J15(3,0) K1(-4,-0.5) K2(-3.5,-0.5) K3(-3,-0.5) K5(-2,-0.5) K6(-1.5,-0.5) K8(-0.5,-0.5) K9(0,-0.5) K10(0.5,-0.5) K12(1.5,-0.5) K13(2,-0.5) K15(3,-0.5) K16(3.5,-0.5) K17(4,-0.5) L2(-3.5,-1) L4(-2.5,-1) L5(-2,-1) L7(-1,-1) L11(1,-1) L13(2,-1) L14(2.5,-1) L16(3.5,-1) M1(-4,-1.5) M2(-3.5,-1.5) M3(-3,-1.5) M4(-2.5,-1.5) M6(-1.5,-1.5) M8(-0.5,-1.5) M10(0.5,-1.5) M12(1.5,-1.5) M14(2.5,-1.5) M15(3,-1.5) M16(3.5,-1.5) M17(4,-1.5) N4(-2.5,-2) N5(-2,-2) N7(-1,-2) N8(-0.5,-2) N10(0.5,-2) N11(1,-2) N13(2,-2) N14(2.5,-2) P1(-4,-2.5) P2(-3.5,-2.5) P3(-3,-2.5) P4(-2.5,-2.5) P6(-1.5,-2.5) P7(-1,-2.5) P9(0,-2.5) P11(1,-2.5) P12(1.5,-2.5) P14(2.5,-2.5) P15(3,-2.5) P16(3.5,-2.5) P17(4,-2.5) R3(-3,-3) R4(-2.5,-3) R5(-2,-3) R6(-1.5,-3) R8(-0.5,-3) R9(0,-3) R10(0.5,-3) R12(1.5,-3) R13(2,-3) R14(2.5,-3) R15(3,-3) T1(-4,-3.5) T2(-3.5,-3.5) T3(-3,-3.5) T4(-2.5,-3.5) T6(-1.5,-3.5) T7(-1,-3.5) T8(-0.5,-3.5) T10(0.5,-3.5) T11(1,-3.5) T12(1.5,-3.5) T14(2.5,-3.5) T15(3,-3.5) T16(3.5,-3.5) T17(4,-3.5) U1(-4,-4) U2(-3.5,-4) U4(-2.5,-4) U6(-1.5,-4) U8(-0.5,-4) U10(0.5,-4) U12(1.5,-4) U14(2.5,-4) U16(3.5,-4) U17(4,-4)
CC0402_25
  round 0.635 smd: 1(-0.508,0) 2(0.508,0)
CC0402_TOL0P15
  rect 0.457x0.61 smd: 1(-0.475,0) 2(0.475,0)
CC0603_OV
  oval 0.889x1.143 smd: 1(-0.762,0) 2(0.762,0)
CON5_JACK_RA_TH
  round 0 hole 1.194 unplated: (-10.3,0) (-3.3,0)
  oval 1.448x2.134 hole 0.813x1.499: 1(0,0)
  oval 2.134x1.448 hole 1.499x0.813: 2(-0.8,2.85) 3(-0.8,-2.85) 4(-8.8,-3.3) 5(-8.8,3.3)
CON16_USB_TYPE-C_RA_TH
  rect 0.66x0.66 hole 0.406: A1(0,0)
  round 0.66 hole 0.406: A4(0.85,0) A5(1.7,0) A6(2.55,0) A7(3.4,0) A8(4.25,0) A9(5.1,0) A12(5.95,0) B1(5.95,-1.35) B4(5.1,-1.35) B5(4.25,-1.35) B6(3.4,-1.35) B7(2.55,-1.35) B8(1.7,-1.35) B9(0.85,-1.35) B12(0,-1.35)
  oval 0.889x2.388 hole 0.61x2.108: SH1(-1.35,-0.98) SH2(7.3,-0.98)
  oval 0.889x1.702 hole 0.61x1.397: SH3(-1.35,-4.36) SH4(7.3,-4.36)
CON_1X8_SKT_2P54_TH_126L
  rect 1.702x1.702 hole 1.016: 1(0,0)
  round 1.702 hole 1.016: 2(0,-2.54) 3(0,-5.08) 4(0,-7.62) 5(0,-10.16) 6(0,-12.7) 7(0,-15.24) 8(0,-17.78)
CON_2X8_SKT_100_TH
  rect 1.651x1.651 hole 1.016: 1(0,0)
  round 1.651 hole 1.016: 2(0,-2.54) 3(2.54,0) 4(2.54,-2.54) 5(5.08,0) 6(5.08,-2.54) 7(7.62,0) 8(7.62,-2.54) 9(10.16,0) 10(10.16,-2.54) 11(12.7,0) 12(12.7,-2.54) 13(15.24,0) 14(15.24,-2.54) 15(17.78,0) 16(17.78,-2.54)
CON_SKT2X6_TH_126L
  rect 1.676x1.676 hole 1.041: 1(0,0)
  round 1.676 hole 1.041: 2(0,2.54) 3(-2.54,0) 4(-2.54,2.54) 5(-5.08,0) 6(-5.08,2.54) 7(-7.62,0) 8(-7.62,2.54) 9(-10.16,0) 10(-10.16,2.54) 11(-12.7,0) 12(-12.7,2.54)
CON_SKT2X10_TH
  rect 1.651x1.651 hole 1.016: 1(0,0)
  round 1.651 hole 1.016: 2(-2.54,0) 3(0,-2.54) 4(-2.54,-2.54) 5(0,-5.08) 6(-2.54,-5.08) 7(0,-7.62) 8(-2.54,-7.62) 9(0,-10.16) 10(-2.54,-10.16) 11(0,-12.7) 12(-2.54,-12.7) 13(0,-15.24) 14(-2.54,-15.24) 15(0,-17.78) 16(-2.54,-17.78) 17(0,-20.32) 18(-2.54,-20.32) 19(0,-22.86) 20(-2.54,-22.86)
CON_SKT2X14_TH_126L
  rect 1.549x1.549 hole 1.041: 1(0,0)
  round 1.549 hole 1.041: 2(-2.54,0) 3(0,-2.54) 4(-2.54,-2.54) 5(0,-5.08) 6(-2.54,-5.08) 7(0,-7.62) 8(-2.54,-7.62) 9(0,-10.16) 10(-2.54,-10.16) 11(0,-12.7) 12(-2.54,-12.7) 13(0,-15.24) 14(-2.54,-15.24) 15(0,-17.78) 16(-2.54,-17.78) 17(0,-20.32) 18(-2.54,-20.32) 19(0,-22.86) 20(-2.54,-22.86) 21(0,-25.4) 22(-2.54,-25.4) 23(0,-27.94) 24(-2.54,-27.94) 25(0,-30.48) 26(-2.54,-30.48) 27(0,-33.02) 28(-2.54,-33.02)
CON_SKT_32F_100_TH
  rect 1.524x1.524 hole 1.041: 1(0,0)
  round 1.524 hole 1.041: 2(-2.54,0) 3(0,-2.54) 4(-2.54,-2.54) 5(0,-5.08) 6(-2.54,-5.08) 7(0,-7.62) 8(-2.54,-7.62) 9(0,-10.16) 10(-2.54,-10.16) 11(0,-12.7) 12(-2.54,-12.7) 13(0,-15.24) 14(-2.54,-15.24) 15(0,-17.78) 16(-2.54,-17.78) 17(0,-20.32) 18(-2.54,-20.32) 19(0,-22.86) 20(-2.54,-22.86) 21(0,-25.4) 22(-2.54,-25.4) 23(0,-27.94) 24(-2.54,-27.94) 25(0,-30.48) 26(-2.54,-30.48) 27(0,-33.02) 28(-2.54,-33.02) 29(0,-35.56) 30(-2.54,-35.56) 31(0,-38.1) 32(-2.54,-38.1)
CSP34_0P5_4P54X1P66
  round 0.229 smd: A1(-2,0.51) A3(-1.5,0.51) A5(-1,0.51) A7(-0.5,0.51) A9(0,0.51) A11(0.5,0.51) A13(1,0.51) A15(1.5,0.51) A17(2,0.51) B2(-1.75,0.17) B4(-1.25,0.17) B6(-0.75,0.17) B8(-0.25,0.17) B10(0.25,0.17) B12(0.75,0.17) B14(1.25,0.17) B16(1.75,0.17) C1(-2,-0.17) C3(-1.5,-0.17) C5(-1,-0.17) C7(-0.5,-0.17) C9(0,-0.17) C11(0.5,-0.17) C13(1,-0.17) C15(1.5,-0.17) C17(2,-0.17) D2(-1.75,-0.51) D4(-1.25,-0.51) D6(-0.75,-0.51) D8(-0.25,-0.51) D10(0.25,-0.51) D12(0.75,-0.51) D14(1.25,-0.51) D16(1.75,-0.51)
DFN_10_0P4_2X2
  rect 0.787x0.229 smd: 1(-0.925,0.8) 2(-0.925,0.4) 3(-0.925,0) 4(-0.925,-0.4) 5(-0.925,-0.8) 6(0.925,-0.8) 7(0.925,-0.4) 8(0.925,0) 9(0.925,0.4) 10(0.925,0.8)
HDR1X2_5P48X2P69
  rect 1.753x1.753 hole 1.118: 1(0,0)
  round 1.753 hole 1.118: 2(2.54,0)
HDR101
  rect 1.676x1.676 hole 1.016: 1(0,0)
HDR103
  rect 1.524x1.524 hole 1.016: 1(0,0)
  round 1.524 hole 1.016: 2(0,-2.54) 3(0,-5.08)
HDR202_100_TH
  rect 1.676x1.676 hole 1.016: 1(0,0)
  round 1.676 hole 1.016: 2(2.54,0) 3(0,-2.54) 4(2.54,-2.54)
HDR_5X2_FTSH_TH
  oval 1.422x1.016 hole 0.711: 1(0,0) 2(1.27,0) 3(0,-1.27) 4(1.27,-1.27) 5(0,-2.54) 6(1.27,-2.54) 7(0,-3.81) 8(1.27,-3.81) 9(0,-5.08) 10(1.27,-5.08)
IND2_2P7X2P2_1P2_SM
  rect 1.092x2.007 smd: 1(0.95,0) 2(-0.95,0)
IND4_CHOKE_0805
  rect 0.914x0.406 smd: 1(-0.85,-0.4) 2(0.85,-0.4) 3(0.85,0.4) 4(-0.85,0.4)
IND_1P8X1MM_SM
  rect 0.991x0.711 smd: 1(-0.845,0) 2(0.845,0)
IND_0402
  round 0.635 smd: 1(-0.508,0) 2(0.508,0)
IND_0805
  rect 1.295x1.499 smd: 1(-0.978,0) 2(0.978,0)
LED4_2P7X2P6_SM
  rect 0.66x0.66 smd: 1(-1.049,-0.65) 2(1.049,-0.65) 3(1.049,0.65) 4(-1.049,0.65)
LED_0603
  rect 0.838x0.787 smd: A(-0.775,0) C(0.775,0)
LGA8_3P1X4P1MM_SPK0641
  rect 0.508x1.016 smd: 1(-0.425,-0.675) 2(-0.425,0.675) 3(0.425,0.675) 4(0.425,-0.675)
  rect 1.321x0.406 smd: 5(0,-1.75) 7(0,1.75)
  rect 0.406x2.311 smd: 6(-1.25,0) 8(1.25,0)
MH125-160
  round 0 hole 3.175 unplated: (0,0)
PHTRANS_1P9X1
  rect 0.813x0.813 smd: 1(-0.75,0) 2(0.75,0)
RC0402_25
  round 0.635 smd: 1(-0.508,0) 2(0.508,0)
RC0402_X3
  round 0.635 smd: 1(-0.508,0) 2(0.508,0) 3(0.508,-1.016)
RC0603_OV
  oval 0.889x1.143 smd: 1(-0.762,0) 2(0.762,0)
RC0805_OV
  oval 0.889x1.524 smd: 1(-0.965,0) 2(0.965,0)
SKT2X6_100_TH_RA
  rect 1.651x1.651 hole 1.016: 1(0,0)
  round 1.651 hole 1.016: 2(2.54,0) 3(0,-2.54) 4(2.54,-2.54) 5(0,-5.08) 6(2.54,-5.08) 7(0,-7.62) 8(2.54,-7.62) 9(0,-10.16) 10(2.54,-10.16) 11(0,-12.7) 12(2.54,-12.7)
SLP1616P6
  rect 0.305x0.635 smd: 1(-0.5,-0.76) 2(0,-0.76) 3(0.5,-0.76) 4(0.5,0.76) 5(0,0.76) 6(-0.5,0.76)
  rect 1.295x0.457 smd: 7(0,0)
SMB_2P7X1P4
  rect 0.813x0.813 smd: A(1.25,0)
  rect 2.007x1.092 smd: C(-0.65,0)
SO8_W
  rect 2.032x0.635 smd: 1(-3.632,1.905) 2(-3.632,0.635) 3(-3.632,-0.635) 4(-3.632,-1.905) 5(3.632,-1.905) 6(3.632,-0.635) 7(3.632,0.635) 8(3.632,1.905)
SOD523
  rect 0.61x0.813 smd: A(0.85,0) C(-0.85,0)
SON8_0P65_3P15X3P15
  custom 0.088x0.088 smd: 1(-1.475,0.975) 2(-1.475,0.325) 3(-1.475,-0.325) 4(-1.475,-0.975) 5(1.475,-0.975) 6(1.475,-0.325) 7(1.475,0.325) 8(1.475,0.975)
  rect 1.6x2.413 smd: 9(0,0)
SOT23-3-1P95
  rect 0.584x1.194 smd: 1(-0.953,-1.25) 2(0.953,-1.25) 3(0,1.25)
SOT89-5
  rect 0.559x1.651 smd: 1(-1.501,-1.501) 3(1.501,-1.501)
  custom 0.437x0.437 smd: 2(0,0)
  rect 0.559x1.524 smd: 4(1.501,1.565) 5(-1.501,1.565)
SOT323_3
  rect 0.406x0.991 smd: 1(0.65,-1.06) 2(-0.65,-1.06) 3(0,1.06)
SOT-23
  rect 1.016x1.397 smd: 1(-0.95,-1.1) 2(0.95,-1.1) 3(0,1.1)
SOT-363_0P65_SMT
  rect 0.762x0.381 smd: 1(-1.085,0.65) 2(-1.085,0) 3(-1.085,-0.65) 4(1.085,-0.65) 5(1.085,0) 6(1.085,0.65)
SW4_4P15_4P2X3P2_SM
  rect 1.041x0.66 smd: 1(-2.015,1.075) 2(2.135,1.075) 3(-2.015,-1.075) 4(2.135,-1.075)
TPAD_040
  round 1.016 smd: 1(0,0)
unnamed#2
  round 1.524 smd: (0,0)
WLCSP12_0P4_1P38X1P68MM_SMDP
  round 0.254 smd: A1(-0.4,0.6) A2(0,0.6) A3(0.4,0.6) B1(-0.4,0.2) B2(0,0.2) B3(0.4,0.2) C1(-0.4,-0.2) C2(0,-0.2) C3(0.4,-0.2) D1(-0.4,-0.6) D2(0,-0.6) D3(0.4,-0.6)
X2QFN12_0P4_1P6X1P6
  rect 0.711x0.203 smd: 1(-0.606,0.2) 2(-0.606,-0.2) 7(0.606,-0.2) 8(0.606,0.2)
  rect 0.203x0.457 smd: 3(-0.6,-0.725) 4(-0.2,-0.725) 5(0.2,-0.725) 6(0.6,-0.725) 9(0.6,0.725) 10(0.2,0.725) 11(-0.2,0.725) 12(-0.6,0.725)
XTAL2-3P2X1P5-SM
  rect 1.092x1.905 smd: 1(-1.25,0) 2(1.25,0)
XTAL4_2P1X1P7MM_SM
  rect 0.864x0.762 smd: 1(-0.675,-0.525) 2(0.675,-0.525) 3(0.675,0.525) 4(-0.675,0.525)
XTAL4_3P4X2P7_SM
  rect 1.397x1.143 smd: 1(-1.1,-0.8) 2(1.1,-0.8) 3(1.1,0.8) 4(-1.1,0.8)

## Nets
AGND: C9.2 C29.2 C31.2 C109.2 R64.2 U1.R6
GND: C1.2 C2.2 C3.2 C4.2 C5.2 C6.2 C7.2 C8.2 C10.2 C11.2 C12.2 C13.2 C14.2 C15.2 C16.2 C17.2 C18.2 C19.2 C20.2 C21.2 C22.2 C23.2 C24.2 C25.2 C26.2 C27.2 C28.2 C30.2 C32.2 C33.2 C34.2 C35.2 C36.2 C38.2 C39.2 C40.2 C41.2 C42.2 C43.2 C44.2 C45.2 C46.2 C47.2 C48.2 C49.2 C50.2 C51.2 C53.2 C54.2 C55.2 C58.1 C59.2 C60.2 C62.2 C63.2 C64.2 C65.2 C66.2 C67.2 C68.2 C69.2 C70.2 C71.2 C72.2 C73.2 C74.2 C75.2 C76.2 C77.2 C78.2 C79.2 C80.2 C81.2 C82.2 C83.2 C85.2 C86.2 C87.2 C88.2 C90.2 C94.2 C95.2 C96.2 C97.2 C98.2 C99.2 C100.2 C101.2 C102.2 C103.2 C104.1 C105.2 C106.2 C107.2 C108.2 C110.2 C111.2 C112.2 C113.2 C114.2 C115.2 C150.2 C154.2 D3.C(CATHODE) D9.A D10.A D11.2 D14.3 J2.14 J3.12 J3.14 J4.3 J5.8 J6.8 J7.9 J7.10 J8.2 J9.22 J10.A1 J10.A12 J10.B1 J10.B12 J10.SH1 J10.SH2 J10.SH3 J10.SH4 J11.A1 J11.A12 J11.B1 J11.B12 J11.SH1 J11.SH2 J11.SH3 J11.SH4 J12.3 J12.5 J13.3 J16.1 J17.1 J19.2 J21.1 J21.2 JP5.1 JP6.1 JP7.1 Q1.1(SOURCE) R64.1 R86.2 R91.2 R93.2 R94.2 R100.1 R111.1 R112.1 R113.2 R122.2 R126.2 R130.2 R132.2 R133.2 R134.2 R135.2 R136.2 R137.2 R149.2 R150.2 R176.1 R178.2 R185.2 R191.2 R197.1 R204.1 R213.2 R214.2 R297.3 SW1.1 SW1.2 SW2.1 SW2.2 SW3.1 SW3.2 U1.D6 U1.D9 U1.D12 U1.E5 U1.E13 U1.G2 U1.H5 U1.H9 U1.H13 U1.J4 U1.J8 U1.J10 U1.J14 U1.K9 U1.N13 U1.P6 U1.P7 U1.P9(VSS_P4_3) U1.P12 U1.P14 U1.P16 U1.T16 U2.2(VSS) U3.1 U4.B3 U4.C3 U4.D3 U5.7 U6.B2 U6.B10 U7.5 U7.6 U7.7 U7.8 U8.B1 U8.B5 U8.B9 U8.B13 U8.H1 U8.H2 U8.J13 U8.M11 U8.M12 U8.N1 U8.N5 U8.N12 U9.7 U10.10 U11.2 U11.9 U12.4 U41.10 Y1.2 Y1.4 Y3.2 Y3.4(GND2)
P3V3_MCU: JP2.1 JP3.2 JP4.2 R71.2 R72.1 R73.1
P5V0: C1.1 C2.1 C5.1 C6.1 C7.1 C38.1 C39.1 D1.C D2.C D4.C J3.10 R179.1 R182.2 R207.1 TP2.1(PIN1) U2.1 U2.4 U3.3 U4.B1 U4.B2 U4.C1(VINT3)
P5V_HDR_IN: C113.1 D4.A J19.3
P5V_MCU_LINK_USB: D2.A L15.2 R121.1 TP13.1(PIN1)
P5V_USB_HS: C40.1 D1.A L3.2 TP14.1(PIN1)
VBAT_DCDC/VBAT_PMU: C75.1 C76.1 C77.1 L13.2 TP17.1(PIN1) U8.M13 U8.N13
VDD_1V8: C8.1 C42.1 J20.1 U3.2(VOUT) U6.B6
VDD_ACCL: C98.1 C99.1 R171.2 R173.1 R174.1 R175.2 R202.1 TP23.1(PIN1) U10.1(VDD)
VDD_AUDIO: C44.1 C45.1 C62.1 R95.2 R203.1 TP18.1(PIN1) U6.B14 U6.D10 U7.4(VDD)
VDD_BOARD: C63.1 C85.1 C106.1 C107.1 C154.1 J3.4 J3.8 J4.1 J7.11 J7.12(B6) J8.1 J9.21 JP1.1 L11.1 L12.1 L13.1 R6.1 R7.1 R43.1 R44.1 R69.2 R87.1 R90.1 R95.1 R118.1 R119.1 R120.1 R125.1 R127.1 R144.1 R145.1 R146.1 R147.1 R157.1 R158.1 R161.1 R162.1 R163.1 R164.1 R166.1 R171.1 R172.2 R180.2 R186.1 R187.1 R188.1 R206.1 R257.1 R265.1 R278.1 R294.1 R297.1 R298.1 R299.1 TP24.1(PIN1) U12.8(VCC) U41.12(VDD)
VDD_CORE: C15.1 C18.1 C19.1 R83.1 R84.2 TP19.1(PIN1) U1.K10 U1.L11
VDD_DCDC: C32.1 R79.2 R80.1 TP25.1(PIN1) U1.R15
VDD_LDO_CORE_IN: C35.1 R84.1 R85.2 TP26.1(PIN1) U1.K6
VDD_LDO_SYS_IN: C30.1 R78.2 R82.1 TP27.1(PIN1) U1.P15
VDD_MCU: C24.1 C25.1 C26.1 C27.1 JP3.1 R24.1 R72.2 R74.1 R75.1 R76.1 R77.1 R78.1 R79.1 R85.1 TP28.1(PIN1) U1.G7 U1.H6 U1.H8
VDD_P2: C21.1 C22.1 C23.1 R77.2 TP29.1(PIN1) U1.K8 U1.L7
VDD_P3: C13.1 C14.1 C16.1 C17.1 R75.2 TP30.1(PIN1) U1.G11 U1.H10 U1.H12
VDD_P4: C10.1 C11.1 C12.1 R74.2 TP31.1(PIN1) U1.N5 U1.P4
VDD_SYS: C28.1 R82.2 TP20.1(PIN1) U1.N14
VDD_USB: C33.1 R24.2 U1.R12
VDD_VBAT: C20.1 R76.2 TP32.1(PIN1) U1.T17
VDDA_MCU: C9.1 C31.1 C109.1 J2.16 L1.2 R23.1 U1.R5
ANA_7/VREFO: C29.1 J2.19 U1.U4
AUX_L: C57.2 U6.C13
AUX_R: C56.2 U6.D14
CAMERA_HSYNC: J9.18(B9) SJ5.2
CAMERA_PCLK: J9.15 SJ4.2
CAN1_H: C104.2 D14.2(CATHODE2) J13.2 R183.1 R184.1
CAN1_H_R: R183.2 U11.7
CAN1_L: C108.1 D14.1 J13.4(B2) R189.2 R190.1
CAN1_L_R: R190.2 U11.6
CAN_VIO_3V3: C101.1 R180.1 R181.1 TP22.1(PIN1) U11.5(VIO)
DBGIF_DETECT: R148.1 U8.E9
DBGIF_ISP0_CTRL: R141.1 U8.C13
DBGIF_RESET: R140.1 U8.E6
DBGIF_TCK_SWCLK: JP8.1 U8.L12
DBGIF_TDI: R143.1 U8.F5
DBGIF_TDO_SWO: R142.1 U8.F8
DBGIF_TMS_SWDIO: R139.1 U8.B11
DBGIF_VREF: C83.1 R125.2 R126.1 TP10.1(PIN1) U8.L1
DCDC_LX: L2.1 R81.2 U1.P17
DCDC_VDD_CORE: C34.1 L2.2 R83.2 TP11.1(PIN1)
HP_L: C49.1 L7.2 U6.A3
HP_R: C46.1 L6.2 U6.A5
HP_S: R97.2 R98.1 R100.2 U6.B4
HS_1: J14.1 R98.2 R102.2
HS_2: J14.2 R97.1 R101.1
HS_USB1_DM: J10.A7 J10.B7 U8.N6 U9.1
HS_USB1_DP: J10.A6 J10.B6 U8.M6 U9.2
HW_VER_0: R130.1 U8.E8
HW_VER_1: R133.1 U8.A8
HW_VER_2: R134.1 U8.F9
HW_VER_3: R135.1 U8.B2
HW_VER_4: R136.1 U8.M5
HW_VER_5: R137.1 U8.H5
HW_VER_6: JP6.2 U8.H9
HW_VER_7: JP7.2 U8.N2
HW_VER_8: R132.1 U8.L13
JTAG_VREF: J12.1 R144.2
LDO_3V3: J15.1 JP1.2 JP2.2 R8.2 R69.1 R70.1 R71.1
LED_USB_COMM: D6.C(CATHODE) U8.F12
LED_VCOM_ACT: D8.C(CATHODE) U8.B6
MCU_HS_USB1_DM: J11.A7 J11.B7 L4.1 U5.1
MCU_HS_USB1_DP: J11.A6 J11.B6 L4.4 U5.2
MCU_LINK_3V3: C64.1 C65.1 C66.1 C67.1 C68.1 C80.1 C81.1 L11.2 R116.1 TP12.1(PIN1) U8.A3 U8.A5 U8.A9 U8.A13 U8.M1 U8.N7
MCU_LINK_I2C0_SCL: R157.2 R159.2 U8.A12
MCU_LINK_I2C0_SDA: R158.2 R160.2 U8.E7
MCU_LINK_N_16MHZ: C78.1 U8.M3 Y1.3
MCU_LINK_P_16MHZ: C79.1 U8.N3 Y1.1
MCU_LINK_RST: R117.2 U8.J6
MCU_LINK_RX: R53.1 R55.1 U8.E12
MCU_LINK_SPI1_MISO: R156.2 U8.G13
MCU_LINK_SPI1_MOSI: R154.2 U8.H12
MCU_LINK_SPI1_SCLK: R153.2 U8.G12
MCU_LINK_SPI1_SSEL: R155.2 U8.B12
MCU_LINK_TX: R216.2 U8.A11
MCU_RESET_B: C86.1 C87.1 D11.1 D12.C(CATHODE) J3.6 J12.10(B5) R140.2 R147.2 R161.2 SW1.3 SW1.4 U1.F3
MCU_UART_RX: R54.1 R56.1 R216.1
MCU_USB1_DM: L4.2 U1.R14
MCU_USB1_DP: L4.3 U1.R13
MIC2_R: C61.2 TP6.1(PIN1) U6.D16
MIC_HDST: C54.1 C61.1 L8.2 R110.2 R113.1
MICBIAS1: C50.1 U6.A15
MICBIAS2: C53.1 R110.1 U6.A17
P0_0/SWDIO: D11.6(K5) J12.2 R139.2 R145.2 U1.A17
P0_1/SWCLK: D11.5 J12.4 JP8.2 R149.1 U1.A16
P0_2/SWO: D11.4 J12.6 R142.2 U1.B16
P0_3/TDI: D11.3 J12.8 R143.2 R146.2 U1.B15
P0_4/SMARTDMA_CAMERA_VSYNC: J9.17 U1.B14
P0_5/SMARTDMA_CAMERA_HSYNC: SJ5.1 U1.A14
P0_6: D9.C J12.7 R2.1 R141.2 U1.C14
P0_6/ISPMODE_N-SW: C88.1 R2.2 R162.2 SW3.3 SW3.4
P0_7/SMARTDMA_CAMERA_PCLK: SJ4.1 U1.C13
P0_14/FXIO_D6: J8.15 U1.E11
P0_15/FXIO_D7: J8.16 U1.G13
P0_16: R5.1 R160.1 U1.B10
P0_16/PDM0_CLK-DMIC: J4.7 R5.2 R96.1 U7.2
P0_17: R4.1 R159.1 U1.A10
P0_17/PDM0_DATA0-DMIC: J4.9 R4.2 R99.1 U7.1
P0_18: J4.5 SJ5.3 U1.C10
P0_19/GPIO: J9.32 U1.C9
P0_20: J8.13 R12.1 U1.C8
P0_20/WUU0_IN4-SW: C90.1 R12.2 R164.2 SW2.3 SW2.4
P0_21: J1.10 J8.14 R13.1 U1.A8
P0_21/ACCL_INT1: R13.2 R173.2 U10.8
P0_22: J1.16(B8) J2.9 U1.B8
P0_23: J2.2 J8.5 R18.1 U1.B7
P0_23/ACCL_WAKEUP: R18.2 U10.7
P0_24: J2.17 J8.8 R14.1 U1.B6
P0_24/ACCL_INT2: R14.2 R174.2 U10.6
P0_25/ADC0_B17-LIGHT_SENSOR: J2.11 R38.2 U1.A6
P0_26/ADC0_B18-MC_VOLT_DCB: J2.7 U1.F10
P0_27/ADC0_B19-MC_BEMF_C: J2.5 U1.E10
P0_28/ADC0_B20-MC_BEMF_B: J2.3 U1.E8
P0_29/ADC0_B21-MC_BEMF_A: J2.1 U1.F8
P1_0: J6.6 J7.3 R15.1 R156.1 U1.C6
P1_0/FC3_SPI_SDO-ARD_D11: R15.2 SJ2.1
P1_1: J2.12 J6.4 J7.7 R153.1 U1.C5
P1_2: J2.10 J6.5 J7.5 R154.1 U1.C4
P1_3: R155.1 SJ1.1 U1.B4
P1_4/SMARTDMA_PIO0-CAMERA_D0: J9.8 U1.A4
P1_5/SMARTDMA_PIO1-CAMERA_D1: J9.7 U1.B3
P1_6/SMARTDMA_PIO2-CAMERA_D2: J9.10 U1.B2
P1_7: J9.9 R22.1 U1.A2
P1_7/SAI1_RX_FS: J1.13 R22.2
P1_8: J9.12 R54.2 U1.A1
P1_9: J9.11 R53.2 U1.B1
P1_10/SMARTDMA_PIO6-CAMERA_D6: J9.14 U1.C3
P1_11/SMARTDMA_PIO7-CAMERA_D7: J9.13 U1.D3
P1_12/SMARTDMA_PIO8: J9.28 U1.D2
P1_13/SMARTDMA_PIO9: J9.27 U1.D1
P1_14/SMARTDMA_PIO10: J9.2 U1.D4
P1_15/SMARTDMA_PIO11: J9.1 U1.E4
P1_16: J6.3 J9.4 R39.1 U1.F6
P1_16/FC5_I2C_SDA-ARD_D18: J2.18 R6.2 R39.2
P1_17: J7.1 J9.3 R40.1 U1.F4
P1_17/FC5_I2C_SCL-ARD_D19: J2.20 R7.2 R40.2
P1_18/SMARTDMA_PIO14-CAMERA_PDOWN: J9.6 U1.G4
P1_19/SMARTDMA_PIO15-CAMERA_RST: J9.5 U1.G5
P1_30/XTAL48M: C96.1 R170.1 U1.F1 Y3.1
P1_31/EXTAL48M: C97.1 R170.2 U1.F2 Y3.3
P2_0: J1.6 SJ3.1 U1.H2
P2_1/GPIO: J9.30 U1.H1
P2_2/CLKOUT-SMARTDMA_CAMERA_CLKIN: J9.16 U1.H3
P2_3/FXIO_D11: J8.20 U1.J3
P2_4/FXIO_D12: J8.21 U1.K3
P2_5/FXIO_D13: J8.22 U1.K1
P2_6/FXIO_D14: J8.23 U1.K2
P2_7: J1.12 J3.13 U1.L2
P2_8/SAI1_TXD0: J1.5 R109.1 U1.M2
P2_9/SAI1_RXD0: J1.15 R107.1 U1.M1
P2_10/SMARTDMA_PIO31: J9.24 U1.M3
P2_11/SMARTDMA_PIO30: J9.26 U1.N4
P3_0/FXIO_D8: J8.17 U1.B17
P3_1/FXIO_D9: J8.18(B9) U1.C15
P3_2/FXIO_D10: J8.19 U1.D15
P3_6/SAI1_MCLK: J1.7 R103.2 U1.D17
P3_7/FXIO_D15: J8.24 U1.D14
P3_8/FXIO_D16: J8.25 U1.E14
P3_9/FXIO_D17: J8.26 U1.F15
P3_10/FXIO_D18: J8.27 U1.F17
P3_11/FXIO_D19: J8.28 U1.F16
P3_12: R35.1 R37.1 U1.G16
P3_12/FC6_QSPI_D3: R35.2 R186.2 U12.7
P3_12/PWM1_A0: J1.8 J3.15 R37.2
P3_13: R36.1 U1.H16
P3_13/FC6_QSPI_D2: R36.2 R188.2 U12.3
P3_14: J2.4 J3.11 U1.H17
P3_15: J3.9 SJ1.3 U1.H15
P3_16: J1.1 J3.7 R106.1 SJ2.3 U1.J15
P3_17: J1.11 J1.14 J3.5 R108.1 SJ3.3 U1.K15
P3_18/SAI1_RX_BCLK: J1.9 U1.K16
P3_20: R32.1 U1.M17
P3_20/FC6_QSPI_D0: R32.2 U12.5
P3_21: R33.1 U1.L16
P3_21/FC6_QSPI_SCK: R33.2 U12.6
P3_22: R34.1 U1.M16
P3_22/FC6_QSPI_D1: R34.2 U12.2
P3_23: R31.1 U1.M15
P3_23/FC6_QSPI_CS0: R31.2 R187.2 U12.1
P4_0: J5.6 J7.8 J8.4 J9.20 R44.2 R49.1 R105.1 R210.2 U1.P1
P4_0/FC2_I2C_SDA-ACCL: R49.2 U10.4
P4_1: J5.5 J7.6 J8.3 J9.19 R43.2 R50.1 R104.1 R211.2 U1.P2
P4_1/FC2_I2C_SCL-ACCL: R50.2 U10.5
P4_2: J1.4 J5.4 R55.2 U1.T1
P4_3: J1.2 J5.3 R56.2 U1.U1
P4_4/SMARTDMA_PIO28: J9.25 U1.M6
P4_5/SMARTDMA_PIO29: J9.23 U1.M8
P4_6: J4.2 J8.6 U1.N7
P4_7/FXIO_LCD_RST: J8.7 U1.T4
P4_12/ARD_A4: J4.10 R299.2 U1.T6
P4_13: J4.12(B6) R57.1 R298.2 U1.T7
P4_13/TRIG_IN8-MC_ENC_B: J3.1 R57.2
P4_14/FXIO_LCD_CS: J8.9 U1.N8
P4_15: J4.4 R25.1 U1.T8
P4_15/CAN1_RXD: R25.2 U11.4
P4_16: J4.6 R67.1 R92.1 U1.R8
P4_16/CAN1_TXD: R67.2 U11.1
P4_17: J4.8 R88.1 R169.2 U1.R9
P4_18: J5.1 R167.2 U1.N10
P4_19: J8.11 R168.2 U1.R10
P4_20/FXIO_LCD_WR: J8.10 U1.T10
P4_21/TRIG_IN9-MC_ENC_A: J3.3 U1.T11
P4_22/FXIO_D30-CAMERA_PCLK: SJ4.3 U1.T12
P4_23/FXIO_LCD_TE: J8.12 U1.U12
P5-9V_VIN: C110.1 C111.1 C112.1 J3.16(B8) J19.1
P5_0/EXTAL32K: C95.1 U1.U16 Y2.2
P5_1/XTAL32K: C94.1 U1.U17 Y2.1
P5_2/MIKROE_RESET: J6.2 U1.M10
P5_3/ADC1_B11-MIKROE_AN: J6.1 U1.N11
P5_4/PMOD_RESET: J7.4 U1.M12
P5_5/PMOD_INT: J7.2 U1.K12
P5_6/MIKROE_INT: J5.2 U1.K13
P5_7: J4.11 R257.2 U1.L13 U41.6
PIO0_5-ISP_EN-LED_SWD_ACT: D7.C(CATHODE) JP5.2 R127.2 U8.A7
SNS_LIGHT_ADC: C100.1 Q2.2(EMITTER) R38.1 R178.1
USB1_CC1: J11.A5 U41.1
USB1_CC2: J11.B5 U41.2
USB1_ID: R93.1 R265.2 R295.1 U1.P11 U5.3 U41.9
USB1_VBUS: R89.2 R91.1 TP15.1(PIN1) U1.U14
USB_OTG_VBUS: C36.1 C41.1 J11.A4 J11.A9 J11.B4(VBUS4) J11.B9 L3.1 R89.1 R276.2 TP16.1(PIN1) U4.C2 U4.D1 U4.D2 U5.6(VBUS)
VDIG: C47.1 U6.D12
VREF_MCULINK: C70.1 C71.1 L12.2 TP21.1(PIN1) U8.G1 U8.G2
N84836: C69.1 R116.2 R117.1
N85250: D6.A R118.2
N85474: D7.A R119.2
N85648: C72.1 C73.1 C74.1 L14.2 U8.M9 U8.N9
N85680: D8.A R120.2
N85830: L14.1 U8.N11
N87448: R121.2 R122.1 U8.N8
N301213: D10.C J12.9 R148.2 R150.1
N383974: D13.3 R168.1
N384008: D13.4(CATHODE3) R169.1
N384038: D13.2 R167.1
N479793: D13.1 R166.2
N629677: D12.A R163.2
N1489105: R87.2 R88.2 U4.A2
N1489467: Q1.3 R90.2 R92.2 U4.A1
N1489479: R94.1 U4.A3
N1493095: C102.1 C103.1 R179.2 U11.3
N1493367: R181.2 R185.1 U11.8
N1493767: J13.1 R182.1
N1493931: C105.1 R184.2 R189.1
N1499275: J2.6 SJ1.2
N1499293: J2.8 SJ2.2
N1499583: J1.3 SJ3.2
N14927971: Q2.1 R172.1
N16628053: C3.1 C4.1 R8.1 U2.5
N16629904: D3.A R70.2
N16780586: JP4.1 L1.1 R73.2
N16872370: C43.1 U6.A9
N16872454: C48.1 U6.B8
N16872595: C51.1 U6.A1
N16872621: C52.1 U6.D2
N16872663: C52.2 U6.C3
N16872673: R103.1 U6.C11
N16872680: C55.1 U6.C1
N16872761: TP9.1(PIN1) U6.A13
N16872798: C58.2 U6.A7
N16873720: L8.1 R101.2 R102.1
N16874336: J14.4 J14.5 L7.1
N16879603: R203.2 R204.2 U7.3
N16880000: C56.1 C59.1 L9.2 R111.2
N16880011: C57.1 C60.1 L10.2 R112.2
N16886184: R96.2 U6.C17
N16886191: R99.2 U6.B16
N16886584: R106.2 U6.D4
N16886590: R107.2 U6.C7
N16886596: R108.2 U6.D6(WCLK)
N16886605: R109.2 U6.C5
N16887090: R105.2 U6.C9
N16887102: R104.2 U6.D8
N16921653: J14.3 L6.1
N16921845: J21.3 L9.1
N16921915: J21.4 J21.5 L10.1
N17029289: R191.1 R202.2 U10.3
N17030310: R175.1 R176.2 U10.2
N17030790: R197.2 U10.9
N17362656: R278.2 U41.11
N17362693: C150.1 R276.1 U41.4
N17362702: R210.1 U41.7
N17362725: R211.1 U41.8
N17363203: R294.2 U41.5
N17363355: R297.2 U41.3
N17363759: Q1.2 R295.2
N17508182: R80.2 R81.1 R86.1
N17592677: C82.1 J10.A4 J10.A9 J10.B4(VBUS4) J10.B9 L15.1 U9.6(VBUS)
N17592697: J10.A5 R214.1
N17592749: J10.B5 R213.1
N17598018: R23.2 U1.R4
N17616471: C114.1 J6.7 R206.2
N17616475: C115.1 J5.7 R207.2
N1687256223: TP8.1(PIN1) U6.B12
N1687256228: TP5.1(PIN1) U6.A11

Pads without a net: J2 13 15; J3 2; J9 29 31; J10 A8 B8; J11 A8 B8; U1 A12 B11 B12 C12 D7 D11 D16 E7 F12 F14 G14 K5 K17 L4 L5 L14 M4 M14 P3 R3 T2 T3 T14 T15 U2 U6 U8 U10; U2 3; U5 4 5; U6 C15; U8 A1 A2 A6 B3 B7 B8 C1 C2 C7 C12 E1 E2 E5 E13 F1 F2 F6 F13 G3 G5 G6 G8 G9 G11 H6 H8 H13 J1 J2 J5 J7 J8 J9 J12 L2 L7 M2 M7 M8; U9 3 4 5

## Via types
v1: diameter 0.508, hole 0.254, TOP to BOTTOM, 524 vias
v2: diameter 0.406, hole 0.203, TOP to BOTTOM, 69 vias
